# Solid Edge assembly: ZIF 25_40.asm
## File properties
Title: Zylinder
Author: bmolnar
Template: iso metric assembly.asm
Last saved by: bmolnar
Revision: 16
Application: Solid Edge
Username: bmolnar
Dokumentum tartalom típus: 1
Document Number: ZIF 25/40
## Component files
Mutter.par
Profilrohr.par
Kolbenstange.par
Kit_2.par
Kit_1.par
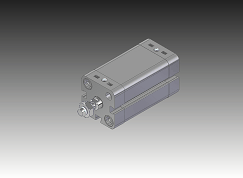
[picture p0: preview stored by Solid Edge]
